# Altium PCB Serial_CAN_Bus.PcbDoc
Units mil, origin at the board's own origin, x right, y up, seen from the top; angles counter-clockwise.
Board outline 1650.02 x 938.19 mil, 2 copper layers (Top, Bottom); 30 components, 25 nets, 114 pads, 65 vias.
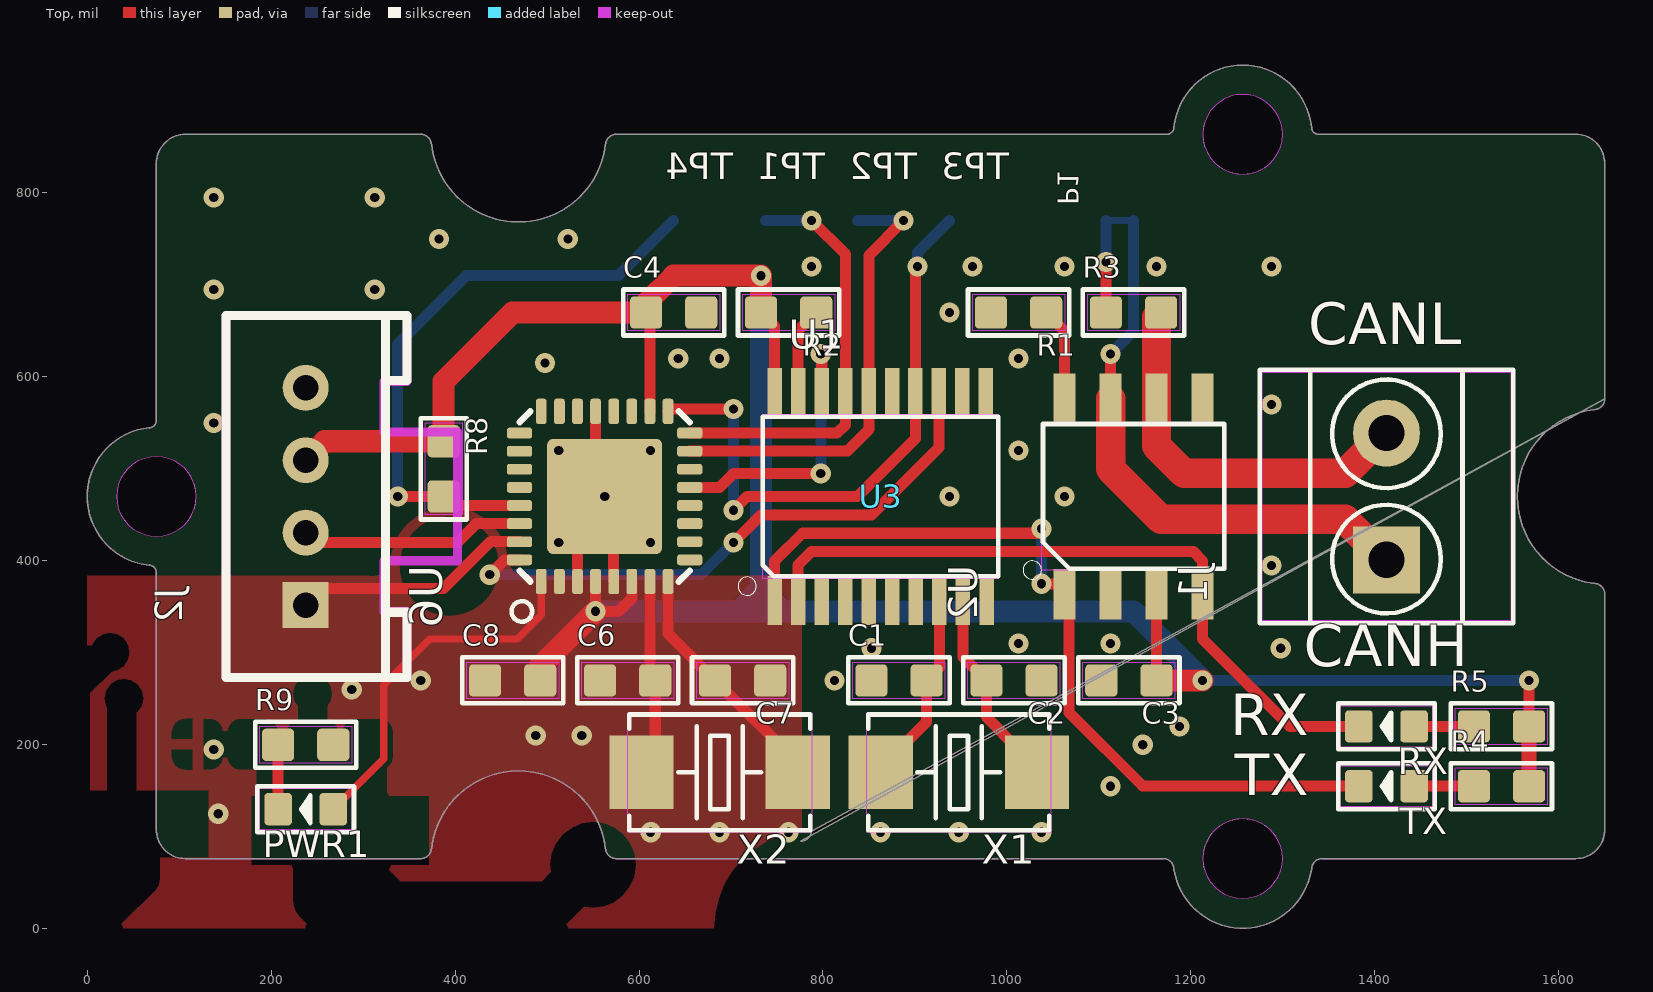
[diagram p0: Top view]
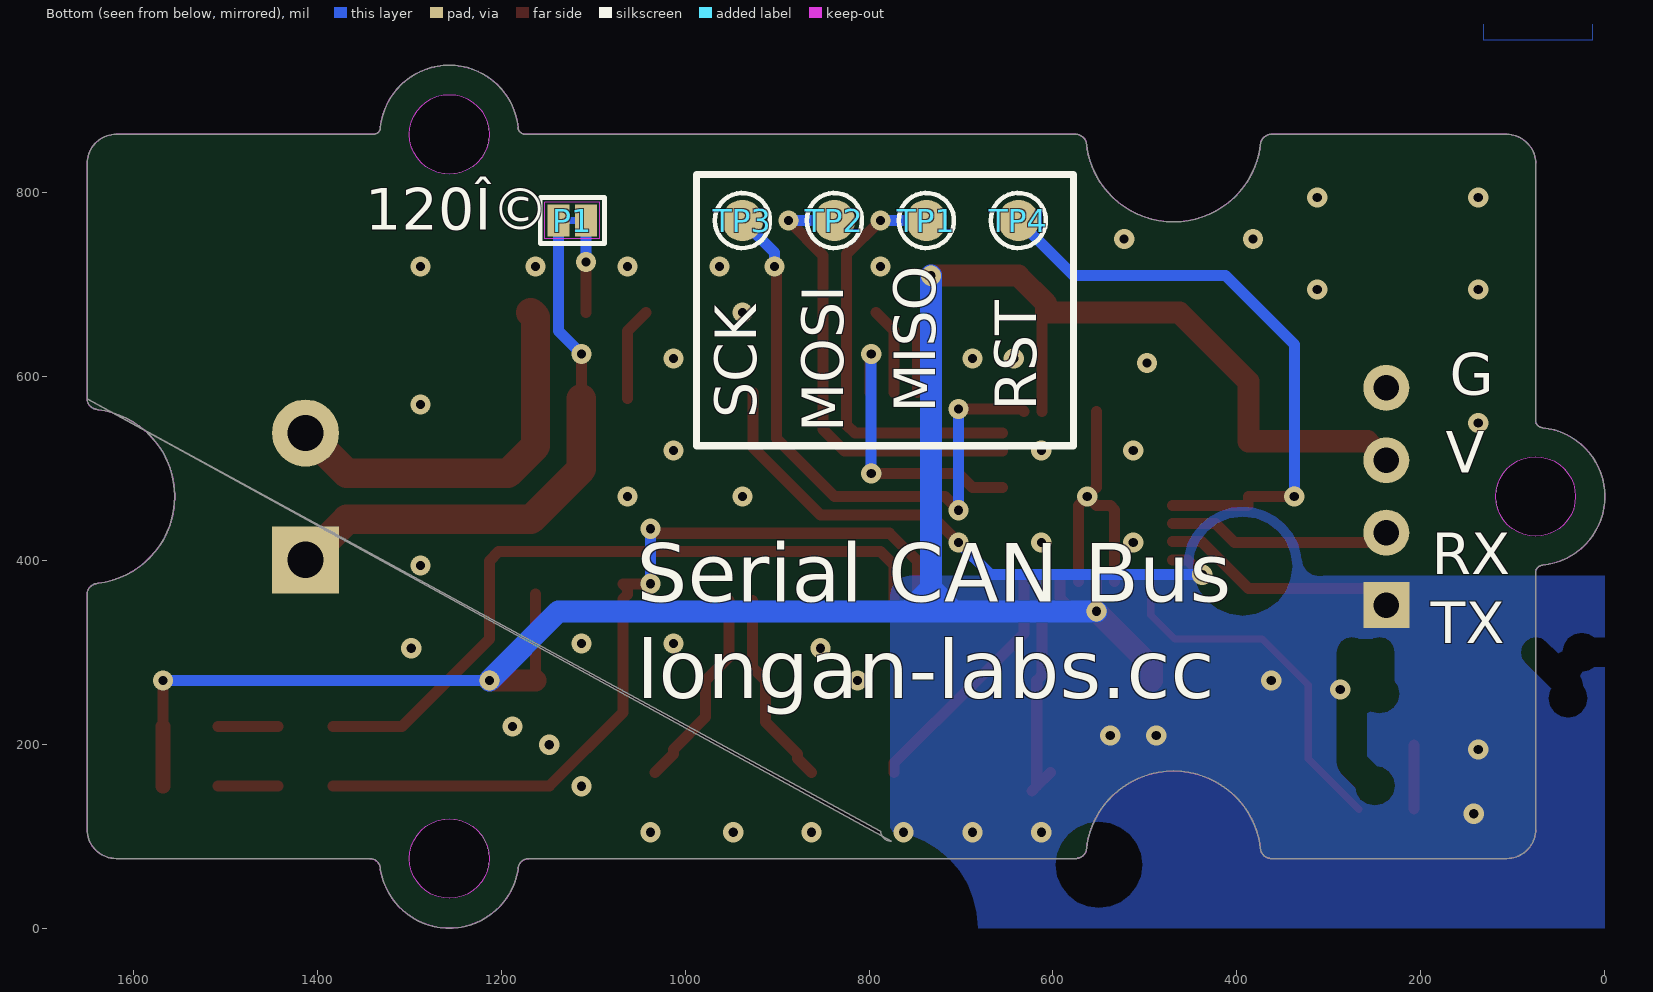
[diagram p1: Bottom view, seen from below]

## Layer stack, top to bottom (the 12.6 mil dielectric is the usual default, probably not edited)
Top Solder: solder mask 0.4, Solder Resist, Dk 3.5
Top: signal copper 1.378
Dielectric 1: dielectric 12.6, FR-4, Dk 4.8
Bottom: signal copper 1.378
Bottom Solder: solder mask 0.4, Solder Resist, Dk 3.5

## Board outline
1650.02,575.73 cw(c1638.21,575.73) 1638.21,563.92 ccw(c1650.02,469.43) 1638.21,374.94 cw(c1638.21,363.13) 1650.02,363.13 1650.02,107.23 cw(c1618.52,107.22) 1618.53,75.73 1342.94,75.73 ccw(c1342.93,63.91) 1331.12,63.92 cw(c1256.32,75.73) 1181.52,63.92 ccw(c1169.71,63.92) 1169.71,75.73 575.22,75.73 cw(c575.22,87.54) 563.41,87.54 ccw(c468.92,75.72) 374.43,87.54 cw(c362.62,87.54) 362.62,75.73 106.71,75.73 cw(c106.71,107.22) 75.22,107.23 75.22,386.75 ccw(c67.34,386.75) 67.34,394.63 cw(c75.21,469.43) 67.34,544.23 ccw(c67.34,552.11) 75.22,552.11 75.22,831.63 cw(c106.71,831.63) 106.71,863.13 362.62,863.13 cw(c362.62,851.32) 374.43,851.32 ccw(c468.92,863.13) 563.41,851.32 cw(c575.22,851.32) 575.22,863.13 1173.64,863.13 ccw(c1173.64,871) 1181.52,871 cw(c1256.32,863.12) 1331.12,871 ccw(c1338.99,871) 1339,863.13 1618.53,863.13 cw(c1618.52,831.63) 1650.02,831.63 1650.02,575.73 cw(c775.59,106.3)
cut-out: 75.22,426.12 ccw(c75.22,469.43) 118.52,469.43 ccw(c75.22,469.43) 75.22,512.73 ccw(c75.22,469.43) 31.91,469.43 ccw(c75.22,469.43)
cut-out: 1256.32,32.42 ccw(c1256.32,75.73) 1299.62,75.73 ccw(c1256.32,75.73) 1256.32,119.03 ccw(c1256.32,75.73) 1213.01,75.73 ccw(c1256.32,75.73)
cut-out: 1256.32,819.82 ccw(c1256.32,863.13) 1299.62,863.13 ccw(c1256.32,863.13) 1256.32,906.43 ccw(c1256.32,863.13) 1213.01,863.13 ccw(c1256.32,863.13)

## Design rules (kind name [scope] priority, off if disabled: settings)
BoardOutlineClearance mdCopperDimension [All] p1: gap=10 ignorepadtopadclearanceinfootprint=FALSE except(0: Arc-SplitContinuation Track-SplitContinuation SMDPad-SplitContinuation THPad-SplitContinuation Via-SplitContinuation Fill-SplitContinuation Poly-SplitContinuation Region-SplitContinuation Text-SplitContinuation)
Clearance Clearance_for_PolygonClass_Isolate_10 [InPolygonClass('Isolate_10') vs IsArc Or IsTrack Or IsPad Or IsVia Or IsFill Or IsRegion Or IsText] p1: gap=10 ignorepadtopadclearanceinfootprint=FALSE
Clearance "Clearance (Same Net)" [All] p2: gap=6 ignorepadtopadclearanceinfootprint=FALSE
Clearance Clearance_for_NetClass_usbvcc [InNetClass('usbvcc') vs InNetClass('usbvcc')] p3: gap=6 ignorepadtopadclearanceinfootprint=FALSE
Clearance [All] p4: gap=6 ignorepadtopadclearanceinfootprint=FALSE
HoleSize HoleSize_For_NetClass_usbvcc [InNetClass('usbvcc')] p1: absolutevalues=TRUE maxlimit=6 minlimit=6 maxpercent=80.000 minpercent=20.000
HoleSize [All] p2: absolutevalues=TRUE maxlimit=100000 minlimit=10 maxpercent=80.000 minpercent=20.000
HoleToHoleClearance mdDrill [All] p1: gap=10 allowstackedmicrovias=TRUE
MinimumSolderMaskSliver [All] p1 off: minsoldermaskwidth=10
PasteMaskExpansion Expansion_SMDPaste_OFF [InPadClass('SMDPaste_OFF')] p1: expansion=0
PasteMaskExpansion mlMinCreamFrame [All] p2: expansion=0
PolygonConnect PolygonConnect_For_PolygonThermal_ON_Width80000_Gap100000 [InPolygonClass('PolygonThermal_ON_Width80000_Gap100000') vs Not IsVia] p1: connectstyle=Relief reliefconductorwidth=8 reliefentries=4 polygonreliefangle="90 Angle" airgapwidth=10
PolygonConnect PolygonConnect_For_PolygonThermal_ON_Width120000_Gap100000 [InPolygonClass('PolygonThermal_ON_Width120000_Gap100000') vs Not IsVia] p2: connectstyle=Relief reliefconductorwidth=12 reliefentries=4 polygonreliefangle="90 Angle" airgapwidth=10
PolygonConnect ThermalVias [IsVia] p3: connectstyle=Direct reliefconductorwidth=10 reliefentries=4 polygonreliefangle="90 Angle" airgapwidth=10
PolygonConnect [All] p4: connectstyle=Relief reliefconductorwidth=10 reliefentries=4 polygonreliefangle="90 Angle" airgapwidth=10
RoutingVias [All] p1: holewidth=10 width=22 viastyle="Through Hole" minholewidth=10 minwidth=22 maxholewidth=100 maxwidth=100
SolderMaskExpansion mlMinStopFrame [All] p1: expansion=2
Width Width_For_NetClass_usbvcc [InNetClass('usbvcc')] p1: maxlimit=10 minlimit=6 preferedwidth=6
Width [All] p2: maxlimit=10000 minlimit=6 preferedwidth=6
26 further rules are at their usual default settings.

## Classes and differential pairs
polygon class PolygonThermal_ON_Width80000_Gap100000: Polygon_1_Net_GND
polygon class PolygonThermal_ON_Width120000_Gap100000: Polygon_2_Net_GND Polygon_3_Net_GND
polygon class Isolate_10: Polygon_2_Net_GND Polygon_3_Net_GND
pad class SMDPaste_OFF: TP1-T TP2-T TP3-T TP4-T U6-HEAT

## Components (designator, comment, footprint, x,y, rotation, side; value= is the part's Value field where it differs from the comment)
C1 "22pF" 0603 882.62,269.43 r0 top
C2 "22pF" 0603 1007.62,269.43 r180 top
C3 "100nF" 0603 1132.62,269.43 r180 top
C4 "100nF" 0603 637.62,669.43 r0 top
C6 "22pF" 0603 587.62,269.43 r0 top
C7 "22pF" 0603 712.62,269.43 r180 top
C8 "100nF" 0603 462.62,269.43 r0 top
J1 "Screw Terminal" 2P-3.5 1412.62,469.43 r90 top
J2 "320110033" HW4-2.0 237.62,469.43 r90 top
P1 "" 2P-SMD-1.78X1.27 1122.62,769.43 r270 bottom
PWR1 "GREEN" LED-0603 237.62,129.43 r180 top
R1 "47k" 0603 1012.62,669.43 r180 top
R2 "10k" 0603 762.62,669.43 r180 top
R3 "120R" 0603 1137.62,669.43 r0 top
R4 "1k" 0603 1537.62,154.43 r0 top
R5 "1k" 0603 1537.62,219.43 r0 top
R8 "10k" 0603 387.62,499.43 r270 top
R9 "1k" 0603 237.62,199.43 r0 top
RX "RED" LED-0603 1412.62,219.43 r180 top
TP1 "" TP_4545 737.62,769.43 r180 bottom
TP2 "" TP_4545 837.62,769.43 r180 bottom
TP3 "" TP_4545 937.62,769.43 r180 bottom
TP4 "" TP_4545 637.62,769.43 r180 bottom
TX "RED" LED-0603 1412.62,154.43 r180 top
U1 "MCP2515" TSSOP20-0.65-6.5X4.4MM 862.62,469.43 r0 top
U2 "MCP2551" SOIC8-6.0 1137.62,469.43 r0 top
U3 "" GROVE-TEST-PLATFORM 862.62,469.43 r180 top
U6 "" MLF32X 562.62,469.43 r90 top
X1 "16MHz" X2-SMD-5.0X3.2X1.3MM 947.62,169.43 r180 top
X2 "16MHz" X2-SMD-5.0X3.2X1.3MM 687.62,169.43 r180 top

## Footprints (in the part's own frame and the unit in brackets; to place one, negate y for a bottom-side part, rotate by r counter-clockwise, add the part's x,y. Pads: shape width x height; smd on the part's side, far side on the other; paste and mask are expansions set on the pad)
2P-3.5 [mm] "2P-3.5"
  rect 1.85x1.85 / inner rect 1.524x1.524 / far side rect 1.85x1.85 hole 1: 1(-1.75,0)
  round 1.85 / inner round 1.524 / far side round 1.85 hole 1: 2(1.75,0)
  Top keep-out region: -3.429,-3.429 -3.429,3.429 3.429,3.429 3.429,-3.429
  silkscreen extent -3.5,-3.5 3.5,3.5
2P-SMD-1.78X1.27 [mil] "2P-SMD-1.78X1.27"
  rect 35x24 smd: 1(0,15) 2(0,-15)
  Top keep-out lines w0: 20,30 20,-30 -20,-30 -20,30 20,30
  silkscreen extent -25,-35 25,35
0603 [mil] "0603"
  rrect25% 35x35 smd: 1(-30,0) 2(30,0)
  Top keep-out region: -50,-20 -50,20 50,20 50,-20
  silkscreen extent -55,-25 55,25
GROVE-TEST-PLATFORM [mil] "GROVE-TEST-PLATFORM"
HW4-2.0 [mm] "HW4-2.0"
  rect 1.27x1.27 / inner rect 1.524x1.524 / far side rect 1.27x1.27 hole 0.7: 1(-3,0)
  round 1.27 / inner round 1.524 / far side round 1.27 hole 0.7: 2(-1,0) 3(1,0) 4(3,0)
  Top keep-out lines w0.254: -4.953,-2.794 -3.175,-2.794 -3.175,-2.159 -1.778,-2.159 -1.778,-4.191 1.778,-4.191 1.778,-2.159 3.175,-2.159 3.175,-2.794 4.953,-2.794 ; -5,-2.8 -5,2.2 5,2.2 5,-2.8
  silkscreen extent -5,-2.8 5,2.2
LED-0603 [mil] "LED-0603"
  rrect25% 30x35 smd: +(-30,0) -(30,0)
  Top keep-out region: -50,-22.5 -50,22.5 50,22.5 50,-22.5
  silkscreen extent -52,-25 52,25
MLF32X [mm] "MLF32X"
  rrect50% 0.7x0.3 smd: 1(-2.35,1.75) 2(-2.35,1.25) 3(-2.35,0.75) 4(-2.35,0.25) 5(-2.35,-0.25) 6(-2.35,-0.75) 7(-2.35,-1.25) 8(-2.35,-1.75) 17(2.35,-1.75) 18(2.35,-1.25) 19(2.35,-0.75) 20(2.35,-0.25) 21(2.35,0.25) 22(2.35,0.75) 23(2.35,1.25) 24(2.35,1.75)
  rrect50% 0.3x0.7 smd: 9(-1.75,-2.35) 10(-1.25,-2.35) 11(-0.75,-2.35) 12(-0.25,-2.35) 13(0.25,-2.35) 14(0.75,-2.35) 15(1.25,-2.35) 16(1.75,-2.35) 25(1.75,2.35) 26(1.25,2.35) 27(0.75,2.35) 28(0.25,2.35) 29(-0.25,2.35) 30(-0.75,2.35) 31(-1.25,2.35) 32(-1.75,2.35)
  rrect10% 3.175x3.175 smd paste-1.587: HEAT(0,0)
  silkscreen extent -3.46,-2.35 2.35,2.57
SOIC8-6.0 [mm] "SOIC8-6.0"
  rect 0.6x1.4 smd: 1(-1.905,-2.7) 2(-0.635,-2.7) 3(0.635,-2.7) 4(1.905,-2.7) 5(1.905,2.7) 6(0.635,2.7) 7(-0.635,2.7) 8(-1.905,2.7)
  Top keep-out region: -2.54,-2.032 -2.54,2.032 2.54,2.032 2.54,-2.032
  silkscreen extent -3.05,-2.29 2.5,2
TP_4545 [mil] "TP_4545"
  rrect100% 45x45 smd paste-22.5: T(0,0)
  silkscreen extent -30,-30 30,30
TSSOP20-0.65-6.5X4.4MM [mm] "TSSOP20-0.65-6.5X4.4MM"
  rect 0.4x1.35 smd: 1(-2.925,-2.875) 2(-2.275,-2.875) 3(-1.625,-2.875) 4(-0.975,-2.875) 5(-0.325,-2.875) 6(0.325,-2.875) 7(0.975,-2.875) 8(1.625,-2.875) 9(2.275,-2.875) 10(2.925,-2.875) 11(2.91,2.875) 12(2.26,2.875) 13(1.61,2.875) 14(0.96,2.875) 15(0.325,2.875) 16(-0.325,2.875) 17(-0.975,2.875) 18(-1.625,2.875) 19(-2.275,2.875) 20(-2.925,2.875)
  Top keep-out region: -3.25,-2.275 -3.25,2.275 3.25,2.275 3.25,-2.275
  silkscreen extent -3.94,-2.73 3.25,2.2
X2-SMD-5.0X3.2X1.3MM [mil] "X2-SMD-5.0X3.2X1.3MM"
  rect 70x80 smd: 1(-85,0) 2(85,0)
  Top keep-out region: -100,-65 -100,65 100,65 100,-65
  silkscreen extent -98,-63 98,63

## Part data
C1 C2 C3 C4 C6 C7 C8 R1 R2 R3 R4 R5 R8 R9: library part 0603
J1: library part 2P-3.5
J2: library part HW4-2.0
P1: library part 2P-SMD-1.78X1.27
PWR1 RX TX: library part LED-0603
TP1 TP2 TP3 TP4: library part TP_4545
U1: library part TSSOP20-0.65-6.5X4.4MM
U2: library part SOIC8-6.0
U3: library part GROVE-TEST-PLATFORM
U6: library part MLF32X
X1 X2: library part X2-SMD-5.0X3.2X1.3MM

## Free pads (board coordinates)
  round 86.61 hole 86.61 unplated: MH1(1256.32,863.13) MH2(1256.32,75.73) MH3(75.22,469.43)

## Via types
v1: diameter 22/22 (per signal layer), hole 10, Top to Bottom, tented both sides, 65 vias

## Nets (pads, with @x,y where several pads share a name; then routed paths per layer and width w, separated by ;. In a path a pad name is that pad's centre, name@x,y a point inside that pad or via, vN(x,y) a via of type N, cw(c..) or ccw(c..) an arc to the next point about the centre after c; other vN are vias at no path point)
CANH: J1.1 P1.2 U2.7 | length 646.3
  Top w12: U2.7 v1(1112.62,624.43)
  Top w32: U2.7 1112.62,499.43 1167.62,444.43 1367.62,444.43 1411.52,400.53 J1.1
  Bottom w8: 1112.62,769.43 P1.2
  Bottom w12: v1(1112.62,624.43) 1137.62,649.43 P1.2
CANL: J1.2 R3.2 U2.6 | length 427.7
  Top w32: R3.2 1162.62,664.43 U2.6 1162.62,524.43 1192.62,494.43 1367.62,494.43 1411.52,538.33 J1.2
GND: C1.1 C2.1 C3.2 C4.2 C6.1 C7.1 C8.1 J2.4 R1.2 R9.2 U1.10 U2.2 U6.3 U6.5 U6.21 U6.HEAT | length 306.9
  Top w12: U6.3 533.09,454.9 537.62,459.43 552.62,459.43 v1(562.62,469.43) ; U6.21 552.78,499.59 552.62,499.43 552.62,479.43 v1(562.62,469.43) ; U6.5 572.46,459.59 v1(562.62,469.43)
  other v1: 612.62,104.43 687.62,104.43 762.62,104.43 862.62,104.43 947.62,104.43 1037.62,104.43 142.62,124.43 1112.62,154.43 137.62,194.43 1147.62,199.43 487.62,209.43 537.62,209.43 1187.62,219.43 287.62,259.43 362.62,269.43 812.62,269.43 852.62,304.43 1297.62,304.43 1012.62,309.43 1112.62,309.43 1287.62,394.43 512.62,419.43 612.62,419.43 937.62,469.43 1062.62,469.43 512.62,519.43 612.62,519.43 1012.62,519.43 137.62,549.43 1287.62,569.43 497.62,614.43 642.62,619.43 687.62,619.43 1012.62,619.43 937.62,669.43 137.62,694.43 312.62,694.43 787.62,719.43 962.62,719.43 1062.62,719.43 1162.62,719.43 1287.62,719.43 382.62,749.43 522.62,749.43 137.62,794.43 312.62,794.43
INT: U1.13 U6.32 | length 644.7
  Top w12: v1(437.62,384.43) 453.72,400.53 U6.32 ; v1(702.62,419.43) 732.62,449.43 852.62,449.43 926.01,522.82 U1.13
  Bottom w12: v1(437.62,384.43) 667.62,384.43 v1(702.62,419.43)
MISO: TP1.T U1.17 U6.16 | length 460.1
  Top w12: U6.16 815.23,538.33 824.23,547.33 U1.17 824.23,732.82 v1(787.62,769.43)
  Bottom w12: TP1.T v1(787.62,769.43)
MOSI: TP2.T U1.16 U6.15 | length 497.4
  Top w12: U6.15 826.47,518.64 849.82,541.99 U1.16 849.82,731.63 v1(887.62,769.43)
  Bottom w12: TP2.T v1(887.62,769.43)
N$1: P1.1 R3.1 | length 100
  Top w12: R3.1 v1(1107.62,724.43)
  Bottom w12: v1(1107.62,724.43) P1.1
N$2: R4.1 TX.+ | length 65
  Top w12: TX.+ R4.1
N$3: C6.2 U6.7 X2.2 | length 253.2
  Top w12: X2.2 X2.2@617.62,154.43 ; U6.7 611.83,275.22 C6.2 X2.2@617.62,154.43 ; X2.2@622.62,149.43 X2.2@617.62,154.43
N$4: C7.2 U6.8 X2.1 | length 265.9
  Top w12: U6.8 631.52,320.53 C7.2 772.62,179.43 X2.1
N$5: R8.2 TP4.T U6.29 | length 663.1
  Top w12: v1(337.62,469.43) R8.2 387.78,459.59 U6.29
  Bottom w12: v1(337.62,469.43) 337.62,634.43 412.62,709.43 577.62,709.43 TP4.T
N$6: PWR1.+ U6.1 | length 396.8
  Top w8: PWR1.+ 322.62,184.43 322.62,264.43 372.62,314.43 467.62,314.43 493.72,340.53 U6.1
N$7: PWR1.- R9.1 | length 70
  Top w12: PWR1.- R9.1
N$15: R5.1 RX.+ | length 65
  Top w12: RX.+ R5.1
N$16: C1.2 U1.8 X1.2 | length 213.3
  Top w12: X1.2 877.62,184.43 877.62,189.43 912.62,224.43 C1.2 926.6,283.41 U1.8
N$17: C2.2 U1.9 X1.1 | length 220.1
  Top w12: U1.9 952.19,294.86 C2.2 977.62,229.43 1012.62,194.43 1012.62,189.43 X1.1
N$20: R1.1 U2.8 | length 102
  Top w12: R1.1 1062.62,649.43 U2.8
RST_N: R2.1 U1.19 | length 94.9
  Top w12: U1.19 773.05,649.86 R2.1
RX: J2.2 U6.30 | length 245.4
  Top w12: J2.2 248.25,419.43 402.62,419.43 423.09,439.9 U6.30
RX_CAN: RX.- U1.2 U2.4 | length 782.7
  Top w12: U1.2 773.05,394.86 787.62,409.43 1202.62,409.43 1212.62,399.43 U2.4 1212.62,314.43 1307.62,219.43 RX.-
SCK: TP3.T U1.14 U6.17 | length 664.8
  Top w12: U6.17 634,564.43 v1(702.62,564.43) ; v1(702.62,454.43) 717.62,469.43 837.62,469.43 900.42,532.23 U1.14 900.42,717.23 v1(902.62,719.43)
  Bottom w12: v1(702.62,454.43) v1(702.62,564.43) ; v1(902.62,719.43) 902.62,734.43 TP3.T
SPI_CS: U1.18 U6.13 | length 321
  Top w12: U6.13 687.46,479.27 702.62,494.43 v1(797.62,494.43) ; v1(797.62,624.43) 798.64,623.41 U1.18
  Bottom w12: v1(797.62,494.43) v1(797.62,624.43)
TX: J2.1 U6.31 | length 261
  Top w12: J2.1 255.73,369.43 387.62,369.43 438.41,420.22 U6.31
TX_CAN: TX.- U1.1 U2.1 | length 930
  Top w12: U1.1 747.46,399.27 777.62,429.43 1032.62,429.43 v1(1037.62,434.43) ; v1(1037.62,374.43) 1067.62,374.43 1062.62,369.43 U2.1 1067.62,358.13 1067.62,234.43 1147.62,154.43 TX.-
  Bottom w12: v1(1037.62,374.43) v1(1037.62,434.43)
VCC: C3.1 C4.1 C8.2 J2.3 R2.2 R4.2 R5.2 R8.1 U1.20 U2.3 U6.4 U6.6 U6.18 | length 2802
  Top w12: U6.4 v1(552.78,344.59) 577.78,344.59 592.15,358.96 U6.6 ; C4.1 611.83,665.22 U6.18 ; R2.2 747.46,654.59 U1.20 ; C3.1 U2.3 ; R5.2 v1(1567.62,269.43)
  Top w16: R4.2 R5.2
  Top w24: J2.3 258.25,529.43 R8.1 387.62,594.43 462.62,669.43 C4.1 607.62,679.43 637.62,709.43 v1(732.62,709.43) 732.62,674.43 R2.2 ; C8.2 492.62,284.43 v1(552.78,344.59) ; C3.1 v1(1212.62,269.43)
  Bottom w12: v1(1212.62,269.43) v1(1567.62,269.43)
  Bottom w24: v1(552.78,344.59) 707.78,344.59 ; v1(732.62,709.43) 732.62,369.43 ; 757.62,344.43 757.46,344.59 ; v1(1212.62,269.43) 1137.46,344.59 757.46,344.59 ; 707.78,344.59 732.62,369.43 ; 707.78,344.59 737.62,344.59 ; 732.62,369.43 757.46,344.59 ; 732.62,369.43 732.62,349.59 737.62,344.59 ; 737.62,344.59 757.46,344.59
pads on no net: U1.3 U1.4 U1.5 U1.6 U1.7 U1.11 U1.12 U1.15 U2.5 U6.2 U6.9 U6.10 U6.11 U6.12 U6.14 U6.19 U6.20 U6.22 U6.23 U6.24 U6.25 U6.26 U6.27 U6.28

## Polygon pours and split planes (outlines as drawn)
GND on Bottom "Polygon_2_Net_GND" (solid, remove dead copper, pour order 2): -18.38,-11.57 1668.62,-11.57 1668.62,950.43 -18.38,950.43
GND on Bottom "Polygon_1_Net_GND" (solid, remove dead copper, pour order 0): 13.62,965.43 131.62,965.43 131.62,1088.43 13.62,1088.43
GND on Top "Polygon_3_Net_GND" (solid, remove dead copper, pour order 1): -18.38,-11.57 1668.62,-11.57 1668.62,950.43 -18.38,950.43

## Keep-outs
Keep-Out Layer:
  the board outline again, w1

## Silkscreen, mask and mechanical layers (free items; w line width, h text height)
Top Overlay:
  text "CANL" at 1327.62,619.43 h77.5
  text "CANH" at 1322.62,269.43 h77.5
  text "RX" at 1242.62,194.43 h77.5
  text "TX" at 1247.62,129.43 h77.5
Bottom Overlay:
  lines w8: 577.62,524.43 987.62,524.43 987.62,819.43 577.62,819.43 577.62,524.43
  text "120Î©" at 1347.62,744.43 h77.5
  text "G" at 168.51,564.76 h77.5
  text "RST" at 602.95,562.66 h77.5 r270
  text "MISO" at 712.95,560.46 h77.5 r270
  text "SCK" at 907.62,554.43 h77.5 r270
  text "MOSI" at 812.62,539.43 h77.5 r270
  text "V" at 172.9,479.76 h77.5
  text "RX" at 188.04,369.76 h77.5
  text "Serial CAN Bus" at 1052.62,334.43 h108.5
  text "TX" at 189.11,294.76 h77.5
  text "longan-labs.cc" at 1052.62,229.43 h108.5
Dimension:
  the board outline again, w1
